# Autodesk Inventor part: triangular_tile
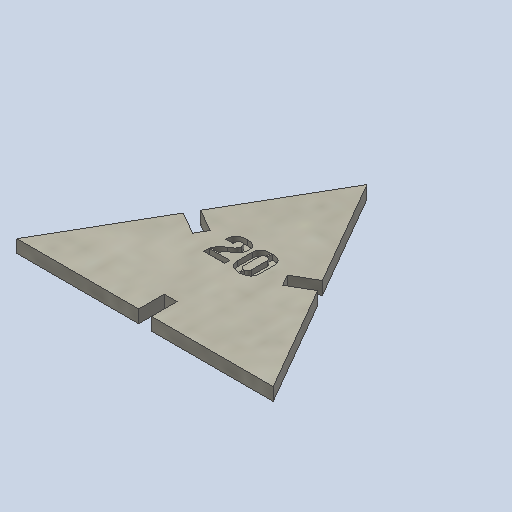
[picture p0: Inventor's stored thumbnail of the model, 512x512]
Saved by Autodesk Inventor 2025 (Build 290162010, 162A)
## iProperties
Created: 2025-02
Part Number: triangular_tile
Material: Paper
Document SubType Name: Modeling
Designer: BennF
Density: 0.93 g/cm^3
Appearance: Cardboard - Chipboard
Author: BennF
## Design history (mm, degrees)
sketch "Sketch2"
  geometry: L1 (-11.875, 3.583)-(0, 24.151); L2 (0, 24.151)-(11.875, 3.583); L3 (11.875, 3.583)-(7.545, 1.083); L4 (7.545, 1.083)-(8.795, -1.083); L5 (8.795, -1.083)-(13.125, 1.417); L6 (13.125, 1.417)-(25, -19.151); L7 (25, -19.151)-(1.25, -19.151); L8 (1.25, -19.151)-(1.25, -14.151); L9 (1.25, -14.151)-(-1.25, -14.151); L10 (-1.25, -14.151)-(-1.25, -19.151); L11 (-1.25, -19.151)-(-25, -19.151); L12 (-13.125, 1.417)-(-8.795, -1.083); L13 (-8.795, -1.083)-(-7.545, 1.083); L14 (-7.545, 1.083)-(-11.875, 3.583); L15 (-13.125, 1.417)-(-25, -19.151); 3 further points
  constraints: 30 end point, 11 perpendicular, 10 equal length, 2 horizontal alignment, 2 midpoint, 2 vertical alignment, 1 horizontal, 1 point on line
  dimensions: "d0" = 2.5 distance of L8.end L9.end (= thickness); "d1" = 5 distance of L7.end L8.end (= slot_depth); "d2" = 50 distance of L6.end L11.end (= tri_side)
extrude "Extrusion1" new body sketch "Sketch2" distance "d4" = 2.5 (= thickness); taper "d5" = 0 deg
sketch "Sketch4"
  geometry: L1 (-5, 5)-(5, 5); L2 (5, 5)-(5, -5); L3 (5, -5)-(-5, -5); L4 (-5, -5)-(-5, 5); L5 (-1.25, -14.151)-(1.25, -14.151) reference; 3 further points
  constraints: 2 midpoint, 1 horizontal alignment, 1 parallel, 1 perpendicular, 1 vertical alignment, 2 other
  dimensions: "d6" = 10 distance of L1.start L1.end
emboss "Emboss1" sketch "Sketch4" dims "d0" = 2.5 (= thickness), "d1" = 5 (= slot_depth), "d2" = 50 (= tri_side), "d7" = 1, "d8" = 0
sketch "laser"
  geometry: L1 (1.678, 1.536)-(1.678, -1.536) reference; L2 (2.274, -2.19)-(2.274, -3.179) reference; L3 (0.248, -1.315)-(0.248, 1.473) reference; L4 (2.274, 3.174)-(2.274, 2.181) reference; L5 (-2.951, -1.812)-(-4.552, -1.812) reference; L6 (-3.127, 1.464)-(-3.149, 1.148) reference; L7 (-3.149, 1.148)-(-4.521, 1.148) reference; L8 (-4.638, -2.033)-(-0.564, -2.033) reference; L9 (-0.564, -2.033)-(-0.564, -3.057) reference; L10 (-0.564, -3.057)-(-4.638, -3.057) reference; L11 (-4.638, -3.057)-(-4.638, -2.033) reference; L12 (3.136, -1.536)-(3.136, 1.536) reference; L13 (2.527, 2.181)-(2.527, 3.183) reference; L14 (4.598, 1.442)-(4.598, -1.347) reference; L15 (2.527, -3.179)-(2.527, -2.19) reference; L16 (-13.125, 1.417)-(-25, -19.151) reference; L17 (-25, -19.151)-(-1.25, -19.151) reference; L18 (-1.25, -19.151)-(-1.25, -14.151) reference; L19 (-1.25, -14.151)-(1.25, -14.151) reference; L20 (1.25, -14.151)-(1.25, -19.151) reference; L21 (1.25, -19.151)-(25, -19.151) reference; L22 (25, -19.151)-(13.125, 1.417) reference; L23 (13.125, 1.417)-(8.795, -1.083) reference; L24 (8.795, -1.083)-(7.545, 1.083) reference; L25 (7.545, 1.083)-(11.875, 3.583) reference; L26 (11.875, 3.583)-(0, 24.151) reference; L27 (0, 24.151)-(-11.875, 3.583) reference; L28 (-11.875, 3.583)-(-7.545, 1.083) reference; L29 (-7.545, 1.083)-(-8.795, -1.083) reference; L30 (-8.795, -1.083)-(-13.125, 1.417) reference; 7 further points
  constraints: 16 other
  node "Projected Loop22"
body "Solid1"
other parameters: "thickness" = 2.5 [user parameter; used in 2 equation terms], "tri_side" = 50 [user parameter; used in 1 equation term], "clearence" = -0.5 [user parameter], "slot_depth" = 5 [user parameter; used in 1 equation term], "slot_dis_1" = 5 [user parameter], "slot_dis_2" = 12 [user parameter], "slot_clearenece" = 3 [user parameter], "con_angle_1" = 20.34444 [user parameter], "con_angle_2" = 60 deg [user parameter], "con_angle_3" = 12.30959 [user parameter], "con_angle_4" = 19.10633 [user parameter], "con_angle_5" = 24.11865 [user parameter], "con_angle_6" = 13.04634 [user parameter]
